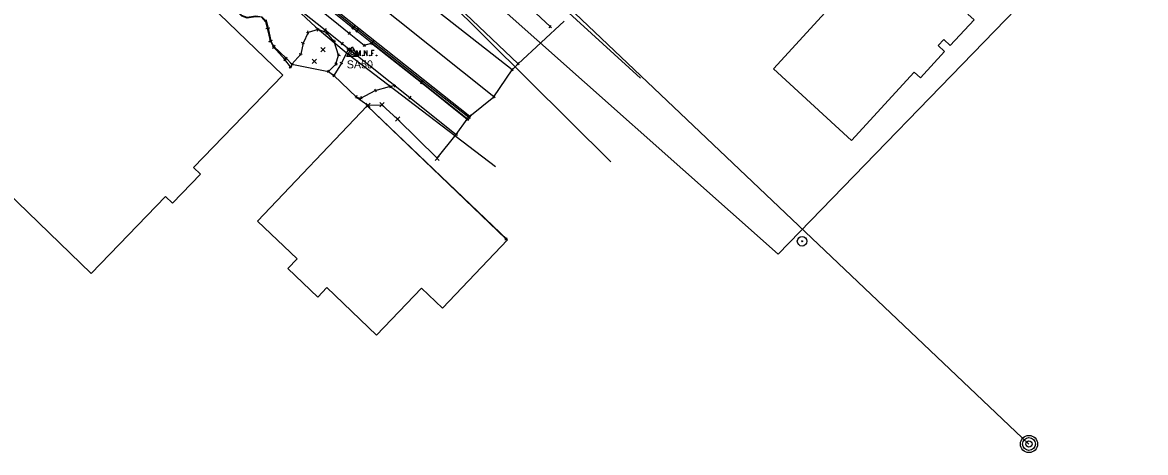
# Model space of a CAD drawing. Extents: x 1475580 to 1482245, y 377937 to 382467.
# Drawn here: x 1481461 to 1481812, y 377956 to 378090.4 of the extents above; entities that cross this region are included whole.
import ezdxf

# ---------------------------------------------------------------- set-up
doc = ezdxf.new("R2010")
doc.units = 0
for name, color, linetype in [('Default', 7, 'Continuous'), ('DT_X_Contour_Major', 7, 'Continuous'), ('DT_X_Void', 7, 'Continuous'), ('PM_P_CL_Double_Solid', 7, 'Continuous'), ('PM_X_Lane_Line', 7, 'Continuous'), ('PV_X_COP', 7, 'Continuous'), ('PV_X_Curb', 7, 'Continuous'), ('PV_X_Walk', 7, 'Continuous'), ('RD_X_Cells', 7, 'Continuous'), ('SG_X_Poles', 7, 'Continuous'), ('SG_X_PullBox', 7, 'Continuous'), ('SN_X_Private', 7, 'Continuous'), ('SN_X_Public', 7, 'Continuous'), ('SV_P_Mon_Cells_Set', 7, 'Continuous'), ('SV_X_Break_Lines', 7, 'Continuous'), ('SV_X_Shot_Marker', 7, 'Continuous'), ('SV_X_Text_Description', 7, 'Continuous'), ('SV_X_Top_of_Bank', 7, 'Continuous'), ('UT_X_Gas_Cells', 7, 'Continuous'), ('UT_X_Misc_Cells', 7, 'Continuous'), ('UT_X_Telecom_Cells', 7, 'Continuous'), ('XS_X_Ground_Line', 7, 'Continuous')]:
    doc.layers.add(name, color=color, linetype=linetype)

msp = doc.modelspace()

# ---------------------------------------------------------------- linework, layer by layer
at = {"layer": 'Default'}
for p, q in [((1481509.14, 378185.06), (1481697.21, 378017.96)), ((1481811.96, 378136.53), (1481697.21, 378017.96)), ((1481586.55, 378104.72), (1481644.93, 378046.85))]:
    msp.add_line(p, q, dxfattribs=at)
msp.add_lwpolyline([(1481559.68, 378163.61), (1481775.54, 377958.65)], dxfattribs=at)
at = {"layer": 'DT_X_Contour_Major'}
for points in [[(1481565.53, 378080), (1481565.53, 378081.6), (1481566.04, 378080), (1481566.53, 378081.6), (1481566.53, 378080)], [(1481567.3, 378080.21), (1481567.35, 378080.21), (1481567.39, 378080.19), (1481567.42, 378080.14), (1481567.42, 378080.07), (1481567.39, 378080.02), (1481567.35, 378080), (1481567.3, 378080), (1481567.27, 378080.02), (1481567.23, 378080.07), (1481567.23, 378080.14), (1481567.27, 378080.19), (1481567.3, 378080.21)], [(1481567.9, 378080), (1481567.9, 378081.6), (1481568.73, 378080), (1481568.73, 378081.6)], [(1481569.51, 378080.21), (1481569.57, 378080.21), (1481569.6, 378080.19), (1481569.63, 378080.14), (1481569.63, 378080.07), (1481569.6, 378080.02), (1481569.57, 378080), (1481569.51, 378080), (1481569.48, 378080.02), (1481569.45, 378080.07), (1481569.45, 378080.14), (1481569.48, 378080.19), (1481569.51, 378080.21)], [(1481570.88, 378081.6), (1481570.12, 378081.6), (1481570.12, 378080)], [(1481570.12, 378080.82), (1481570.66, 378080.82)], [(1481571.66, 378080.21), (1481571.72, 378080.21), (1481571.75, 378080.19), (1481571.78, 378080.14), (1481571.78, 378080.07), (1481571.75, 378080.02), (1481571.72, 378080), (1481571.66, 378080), (1481571.63, 378080.02), (1481571.6, 378080.07), (1481571.6, 378080.14), (1481571.63, 378080.19), (1481571.66, 378080.21)]]:
    msp.add_lwpolyline(points, dxfattribs=at)
msp.add_circle((1481564.09, 378080.81), 0.497, dxfattribs=at)
at = {"layer": 'DT_X_Void'}
for p, q in [((1481562.36, 378079.81), (1481564.09, 378082.81)), ((1481565.83, 378079.81), (1481562.36, 378079.81)), ((1481564.09, 378082.81), (1481565.83, 378079.81)), ((1481564.09, 378080.81), (1481564.09, 378080.81))]:
    msp.add_line(p, q, dxfattribs=at)
msp.add_circle((1481564.09, 378080.81), 1, dxfattribs=at)
at = {"layer": 'PM_P_CL_Double_Solid'}
msp.add_lwpolyline([(1481328.89, 378378.54), (1481440.38, 378283.94), (1481522.63, 378196), (1481603.5, 378119.27), (1481654.2, 378073)], dxfattribs=at)
at = {"layer": 'PM_X_Lane_Line'}
for radius in [1.5, 0.16]:
    msp.add_circle((1481704.65, 378022.02), radius, dxfattribs=at)
at = {"layer": 'PV_X_COP'}
for points in [[(1481562.85, 378081.94), (1481560.71, 378077.68), (1481558.31, 378073.83)], [(1481565.37, 378067.11), (1481566.71, 378066.77), (1481571.28, 378069.14), (1481575.74, 378070.41), (1481577.18, 378070.68)]]:
    msp.add_lwpolyline(points, dxfattribs=at)
at = {"layer": 'PV_X_Curb'}
for p, q in [((1481554.28, 378081.26), (1481555.61, 378082.6)), ((1481554.28, 378082.6), (1481555.61, 378081.26)), ((1481551.56, 378077.62), (1481552.9, 378078.95)), ((1481551.56, 378078.95), (1481552.9, 378077.62)), ((1481568.31, 378063.84), (1481569.64, 378065.18)), ((1481568.31, 378065.18), (1481569.64, 378063.84)), ((1481572.68, 378064.01), (1481574.01, 378065.35)), ((1481572.68, 378065.35), (1481574.01, 378064.01)), ((1481577.57, 378059.55), (1481578.91, 378060.89)), ((1481577.57, 378060.89), (1481578.91, 378059.55)), ((1481589.94, 378047.3), (1481591.27, 378048.64)), ((1481589.94, 378048.64), (1481591.27, 378047.3))]:
    msp.add_line(p, q, dxfattribs=at)
at = {"layer": 'PV_X_Walk'}
for p, q in [((1481775.54, 377960.65), (1481775.54, 377960.65)), ((1481775.54, 377958.65), (1481775.54, 377958.65)), ((1481775.54, 377958.65), (1481775.54, 377958.65)), ((1481775.54, 377958.65), (1481775.54, 377958.65)), ((1481775.54, 377956.65), (1481775.54, 377956.65))]:
    msp.add_line(p, q, dxfattribs=at)
msp.add_circle((1481775.54, 377958.65), 2, dxfattribs=at)
at = {"layer": 'RD_X_Cells'}
for points in [[(1481458.52, 378183.21), (1481462.55, 378180.65), (1481464.81, 378178.65), (1481466.55, 378177.09), (1481469.53, 378174.15), (1481471.49, 378172.33), (1481472.88, 378171.04), (1481473.75, 378170.22), (1481472.82, 378168.55), (1481490.35, 378151.83), (1481495.08, 378147.37), (1481513.59, 378129.71), (1481521.15, 378122.57), (1481534.36, 378110.14), (1481539.71, 378105.82), (1481558.14, 378091.1), (1481563.12, 378087.08), (1481567.81, 378083.28), (1481570.12, 378083.9), (1481585.68, 378071.65), (1481600.01, 378060.19)], [(1481460.59, 378174.73), (1481462.49, 378172.93), (1481465.52, 378170.07), (1481467.45, 378168.13), (1481469.02, 378166.75), (1481469.94, 378165.76), (1481487.85, 378148.78), (1481492.26, 378144.63), (1481510.84, 378126.93), (1481518.37, 378119.73), (1481531.89, 378107.04), (1481537.21, 378102.75), (1481555.6, 378088.12), (1481560.89, 378083.85), (1481563.14, 378082.04), (1481582.04, 378066.96), (1481596.55, 378055.44)]]:
    msp.add_lwpolyline(points, dxfattribs=at)
at = {"layer": 'SG_X_Poles'}
msp.add_lwpolyline([(1481443.23, 378191.33), (1481460.58, 378174.71), (1481460.58, 378174.71), (1481552.62, 378089.05), (1481562.79, 378080.54), (1481608.89, 378045.37)], dxfattribs=at)
at = {"layer": 'SG_X_PullBox'}
for radius in [2.67, 2, 1]:
    msp.add_circle((1481775.54, 377958.65), radius, dxfattribs=at)
at = {"layer": 'SN_X_Private'}
msp.add_lwpolyline([(1481556.67, 378075.13), (1481558.99, 378077.38), (1481559.83, 378080.22), (1481558.44, 378084.49), (1481556.16, 378087.15), (1481553.46, 378088.2), (1481550.29, 378087.28), (1481548.7, 378083.9), (1481547.99, 378080.54), (1481545.19, 378077.34), (1481543.4, 378079.23), (1481539.6, 378082.91), (1481538.67, 378084.61), (1481537.82, 378088.62), (1481537.33, 378090.71), (1481535.9, 378092.09), (1481533.85, 378092.42), (1481531.25, 378091.92), (1481529.54, 378092.55), (1481525.83, 378096.48)], dxfattribs=at)
at = {"layer": 'SN_X_Public'}
msp.add_lwpolyline([(1481608.37, 378067.18), (1481558.31, 378107.18), (1481537.72, 378124.16), (1481479.82, 378179.17)], dxfattribs=at)
at = {"layer": 'SV_P_Mon_Cells_Set'}
for points in [[(1481451.97, 378161.26), (1481473.67, 378140.29), (1481475.51, 378142.19), (1481484.73, 378133.29), (1481482.89, 378131.39), (1481542.37, 378073.94), (1481514.51, 378045.1), (1481516.7, 378042.98), (1481507.91, 378033.89), (1481505.73, 378035.99), (1481482.51, 378011.95), (1481423.22, 378069.23), (1481422, 378067.97), (1481413.02, 378076.65), (1481414.23, 378077.9), (1481392.1, 378099.28)], [(1481752.53, 378137.81), (1481775.2, 378116.97), (1481774.2, 378115.07), (1481772.46, 378110.43), (1481756.45, 378093.02), (1481758.37, 378091.26), (1481750.96, 378083.2), (1481748.91, 378085.09), (1481747.15, 378083.18), (1481749.17, 378081.33), (1481741.6, 378073.1), (1481739.7, 378074.84), (1481720.13, 378053.55), (1481695.75, 378075.96), (1481713.04, 378094.77), (1481710.72, 378096.9), (1481717.63, 378104.41), (1481719.97, 378102.26), (1481727.98, 378110.97), (1481725.96, 378112.83), (1481733, 378120.48), (1481734.95, 378118.69)], [(1481612.64, 378022.48), (1481592.25, 378001.1), (1481585.69, 378007.35), (1481571.67, 377992.66), (1481556.09, 378007.52), (1481553.28, 378004.58), (1481543.94, 378013.49), (1481546.82, 378016.52), (1481534.44, 378028.33), (1481568.76, 378064.32)]]:
    msp.add_lwpolyline(points, close=True, dxfattribs=at)
msp.add_lwpolyline([(1481568.76, 378064.32), (1481612.1, 378022.77)], dxfattribs=at)
at = {"layer": 'SV_X_Break_Lines'}
for points in [[(1481614.01, 378075.61), (1481567.93, 378111.83), (1481558.93, 378119.06), (1481551.14, 378125.65), (1481539.73, 378135.95), (1481513.59, 378160.95), (1481485.53, 378187.47)], [(1481615.92, 378077.49), (1481566.67, 378124.35), (1481560.41, 378129.93), (1481553.77, 378135), (1481547.01, 378139.33), (1481513.59, 378160.95)]]:
    msp.add_lwpolyline(points, dxfattribs=at)
at = {"layer": 'SV_X_Shot_Marker'}
msp.add_lwpolyline([(1481473.05, 378172.31), (1481522.89, 378125.39), (1481530.28, 378118.34), (1481538.45, 378111.25), (1481547.66, 378103.47), (1481557.62, 378095.38), (1481600.78, 378061.17)], dxfattribs=at)
at = {"layer": 'SV_X_Text_Description'}
msp.add_lwpolyline([(1481522.36, 378124.13), (1481535.77, 378111.48), (1481540.63, 378107.49), (1481559.35, 378092.66), (1481564.22, 378088.75), (1481565.47, 378087.79), (1481570.18, 378084.03), (1481585.76, 378071.75), (1481600.14, 378060.3)], dxfattribs=at)
at = {"layer": 'SV_X_Top_of_Bank'}
msp.add_lwpolyline([(1481537.33, 378090.71), (1481537.82, 378088.62), (1481538.67, 378084.61), (1481539.6, 378082.91), (1481543.4, 378079.23), (1481545.19, 378077.34), (1481556.67, 378075.13), (1481558.31, 378073.83), (1481565.37, 378067.11), (1481568.98, 378064.51), (1481573.34, 378064.68), (1481578.24, 378060.22), (1481590.61, 378047.97), (1481596.55, 378055.44), (1481600.01, 378060.19), (1481600.14, 378060.3), (1481600.51, 378060.76), (1481600.78, 378061.17), (1481608.37, 378067.18), (1481614.01, 378075.61), (1481615.92, 378077.49), (1481630.31, 378090.85)], dxfattribs=at)
at = {"layer": 'UT_X_Gas_Cells'}
for p, q in [((1481537.24, 378090.15), (1481537.01, 378091.12)), ((1481537.45, 378090.23), (1481537.22, 378091.2)), ((1481537.12, 378088.5), (1481538.1, 378088.72)), ((1481537.33, 378088.51), (1481538.31, 378088.72)), ((1481537.72, 378088.12), (1481537.5, 378089.09)), ((1481537.61, 378088.61), (1481537.61, 378088.61)), ((1481537.93, 378088.13), (1481537.72, 378089.11)), ((1481537.82, 378088.62), (1481537.82, 378088.62)), ((1481550.77, 378087.42), (1481549.81, 378087.13)), ((1481550.43, 378086.8), (1481550.15, 378087.75)), ((1481550.29, 378087.28), (1481550.29, 378087.28)), ((1481553.92, 378088.02), (1481552.99, 378088.38)), ((1481553.27, 378087.73), (1481553.64, 378088.66)), ((1481553.46, 378088.2), (1481553.46, 378088.2)), ((1481555.21, 378088.43), (1481555.99, 378087.8)), ((1481555.91, 378088.51), (1481555.28, 378087.72)), ((1481555.6, 378088.12), (1481555.6, 378088.12)), ((1481555.78, 378086.82), (1481556.54, 378087.47)), ((1481556.48, 378086.77), (1481555.83, 378087.53)), ((1481556.16, 378087.15), (1481556.16, 378087.15)), ((1481562.73, 378087.39), (1481563.51, 378086.77)), ((1481563.43, 378087.47), (1481562.8, 378086.69)), ((1481563.12, 378087.08), (1481563.12, 378087.08)), ((1481563.83, 378089.06), (1481564.61, 378088.43)), ((1481564.54, 378089.14), (1481563.91, 378088.36)), ((1481564.22, 378088.75), (1481564.22, 378088.75)), ((1481564.28, 378089.38), (1481565.06, 378088.76)), ((1481564.98, 378089.46), (1481564.36, 378088.68)), ((1481564.67, 378089.07), (1481564.67, 378089.07)), ((1481565.08, 378088.09), (1481565.87, 378087.48)), ((1481565.78, 378088.18), (1481565.17, 378087.39)), ((1481565.46, 378088.47), (1481566.26, 378087.86)), ((1481565.47, 378087.79), (1481565.47, 378087.79)), ((1481566.16, 378088.56), (1481565.56, 378087.77)), ((1481565.86, 378088.17), (1481565.86, 378088.17)), ((1481626.29, 378088.76), (1481625.56, 378089.44)), ((1481625.59, 378088.73), (1481626.27, 378089.47)), ((1481625.93, 378089.1), (1481625.93, 378089.1)), ((1481538.06, 378084.44), (1481538.95, 378084.9)), ((1481538.23, 378084.38), (1481539.11, 378084.85)), ((1481538.74, 378084.23), (1481538.28, 378085.12)), ((1481538.91, 378084.18), (1481538.43, 378085.05)), ((1481538.51, 378084.67), (1481538.51, 378084.67)), ((1481538.67, 378084.61), (1481538.67, 378084.61)), ((1481539.96, 378082.56), (1481539.24, 378083.26)), ((1481539.25, 378082.55), (1481539.95, 378083.27)), ((1481549.15, 378083.69), (1481548.25, 378084.12)), ((1481548.91, 378084.36), (1481548.48, 378083.45)), ((1481548.7, 378083.9), (1481548.7, 378083.9)), ((1481557.97, 378084.33), (1481558.92, 378084.64)), ((1481558.6, 378084.01), (1481558.29, 378084.96)), ((1481558.44, 378084.49), (1481558.44, 378084.49)), ((1481560.5, 378084.16), (1481561.28, 378083.53)), ((1481561.21, 378084.24), (1481560.58, 378083.46)), ((1481560.89, 378083.85), (1481560.89, 378083.85)), ((1481567.42, 378083.6), (1481568.2, 378082.97)), ((1481568.13, 378083.67), (1481567.5, 378082.89)), ((1481567.81, 378083.28), (1481567.81, 378083.28)), ((1481569.64, 378083.77), (1481570.6, 378084.03)), ((1481569.79, 378084.34), (1481570.57, 378083.72)), ((1481570.49, 378084.42), (1481569.87, 378083.64)), ((1481569.99, 378084.38), (1481570.25, 378083.42)), ((1481570.12, 378083.9), (1481570.12, 378083.9)), ((1481570.16, 378084.81), (1481570.95, 378084.19)), ((1481570.18, 378084.03), (1481570.18, 378084.03)), ((1481570.86, 378084.89), (1481570.25, 378084.1)), ((1481570.56, 378084.5), (1481570.56, 378084.5)), ((1481539.19, 378082.3), (1481539.93, 378082.98)), ((1481539.9, 378082.27), (1481539.22, 378083.01)), ((1481539.56, 378082.64), (1481539.56, 378082.64)), ((1481539.6, 378082.91), (1481539.6, 378082.91)), ((1481543.03, 378078.89), (1481543.76, 378079.58)), ((1481543.74, 378078.87), (1481543.05, 378079.59)), ((1481548.48, 378080.44), (1481547.5, 378080.64)), ((1481548.09, 378081.03), (1481547.89, 378080.05)), ((1481547.99, 378080.54), (1481547.99, 378080.54)), ((1481559.35, 378080.36), (1481560.31, 378080.08)), ((1481559.69, 378079.74), (1481559.97, 378080.7)), ((1481559.83, 378080.22), (1481559.83, 378080.22)), ((1481563.29, 378081.72), (1481562.4, 378082.17)), ((1481563.07, 378082.39), (1481562.62, 378081.5)), ((1481562.75, 378082.35), (1481563.53, 378081.73)), ((1481563.45, 378082.43), (1481562.82, 378081.65)), ((1481562.85, 378081.94), (1481562.85, 378081.94)), ((1481563.14, 378082.04), (1481563.14, 378082.04)), ((1481542.65, 378078.52), (1481543.45, 378079.13)), ((1481543.35, 378078.43), (1481542.75, 378079.23)), ((1481543.05, 378078.83), (1481543.05, 378078.83)), ((1481543.4, 378079.23), (1481543.4, 378079.23)), ((1481544.36, 378076.26), (1481545.16, 378076.87)), ((1481545.06, 378076.17), (1481544.46, 378076.96)), ((1481544.76, 378076.56), (1481544.76, 378076.56)), ((1481545.57, 378077.01), (1481544.81, 378077.67)), ((1481545.52, 378077.71), (1481544.86, 378076.96)), ((1481545.19, 378077.34), (1481545.19, 378077.34)), ((1481558.63, 378077.03), (1481559.35, 378077.73)), ((1481558.64, 378077.74), (1481559.33, 378077.02)), ((1481558.99, 378077.38), (1481558.99, 378077.38)), ((1481561.16, 378077.45), (1481560.27, 378077.9)), ((1481560.94, 378078.13), (1481560.49, 378077.23)), ((1481560.71, 378077.68), (1481560.71, 378077.68)), ((1481616.28, 378077.15), (1481615.56, 378077.84)), ((1481615.58, 378077.13), (1481616.27, 378077.86)), ((1481615.92, 378077.49), (1481615.92, 378077.49)), ((1481556.31, 378074.79), (1481557.03, 378075.48)), ((1481556.32, 378075.49), (1481557.01, 378074.77)), ((1481556.67, 378075.13), (1481556.67, 378075.13)), ((1481558.73, 378073.57), (1481557.88, 378074.1)), ((1481558.57, 378074.26), (1481558.04, 378073.41)), ((1481558.31, 378073.83), (1481558.31, 378073.83)), ((1481585.63, 378072.52), (1481586.41, 378071.9)), ((1481586.33, 378072.6), (1481585.71, 378071.82)), ((1481614.41, 378075.3), (1481613.62, 378075.92)), ((1481613.7, 378075.22), (1481614.32, 378076)), ((1481614.01, 378075.61), (1481614.01, 378075.61)), ((1481570.84, 378068.91), (1481571.73, 378069.37)), ((1481571.05, 378069.58), (1481571.51, 378068.69)), ((1481571.28, 378069.14), (1481571.28, 378069.14)), ((1481575.26, 378070.27), (1481576.22, 378070.55)), ((1481575.6, 378070.89), (1481575.88, 378069.93)), ((1481575.74, 378070.41), (1481575.74, 378070.41)), ((1481576.69, 378070.59), (1481577.67, 378070.77)), ((1481577.09, 378071.17), (1481577.27, 378070.19)), ((1481577.18, 378070.68), (1481577.18, 378070.68)), ((1481585.28, 378071.96), (1481586.07, 378071.34)), ((1481585.37, 378072.06), (1481586.15, 378071.44)), ((1481585.99, 378072.04), (1481585.37, 378071.25)), ((1481586.07, 378072.14), (1481585.45, 378071.36)), ((1481585.68, 378071.65), (1481585.68, 378071.65)), ((1481585.76, 378071.75), (1481585.76, 378071.75)), ((1481586.02, 378072.21), (1481586.02, 378072.21)), ((1481564.89, 378067.23), (1481565.86, 378066.98)), ((1481565.5, 378067.59), (1481565.25, 378066.62)), ((1481565.37, 378067.11), (1481565.37, 378067.11)), ((1481566.23, 378066.89), (1481567.2, 378066.65)), ((1481566.84, 378067.25), (1481566.59, 378066.28)), ((1481566.71, 378066.77), (1481566.71, 378066.77)), ((1481581.65, 378067.28), (1481582.43, 378066.65)), ((1481582.35, 378067.36), (1481581.73, 378066.57)), ((1481582.04, 378066.96), (1481582.04, 378066.96)), ((1481608.76, 378066.87), (1481607.98, 378067.49)), ((1481608.06, 378066.79), (1481608.68, 378067.57)), ((1481608.37, 378067.18), (1481608.37, 378067.18)), ((1481568.4, 378064.67), (1481569.13, 378063.97)), ((1481569.11, 378064.68), (1481568.42, 378063.96)), ((1481568.76, 378064.32), (1481568.76, 378064.32)), ((1481599.62, 378060.5), (1481600.4, 378059.88)), ((1481600.32, 378060.58), (1481599.7, 378059.8)), ((1481599.75, 378060.61), (1481600.53, 378059.99)), ((1481600.45, 378060.69), (1481599.83, 378059.91)), ((1481600.01, 378060.19), (1481600.01, 378060.19)), ((1481600.12, 378061.07), (1481600.9, 378060.44)), ((1481600.14, 378060.3), (1481600.14, 378060.3)), ((1481600.82, 378061.15), (1481600.2, 378060.36)), ((1481600.38, 378061.48), (1481601.17, 378060.86)), ((1481601.09, 378061.56), (1481600.46, 378060.78)), ((1481600.51, 378060.76), (1481600.51, 378060.76)), ((1481600.78, 378061.17), (1481600.78, 378061.17)), ((1481596.16, 378055.75), (1481596.94, 378055.13)), ((1481596.86, 378055.83), (1481596.24, 378055.05)), ((1481596.55, 378055.44), (1481596.55, 378055.44)), ((1481611.74, 378023.11), (1481612.46, 378022.42)), ((1481612.45, 378023.13), (1481611.76, 378022.4)), ((1481612.1, 378022.77), (1481612.1, 378022.77))]:
    msp.add_line(p, q, dxfattribs=at)
at = {"layer": 'UT_X_Misc_Cells'}
msp.add_lwpolyline([(1481544.76, 378076.56), (1481543.05, 378078.83), (1481539.56, 378082.64), (1481538.51, 378084.67), (1481537.61, 378088.61), (1481537.12, 378090.63), (1481535.84, 378092.02), (1481533.84, 378092.16), (1481531.28, 378091.74), (1481529.57, 378092.34), (1481525.67, 378096.09)], dxfattribs=at)
at = {"layer": 'UT_X_Telecom_Cells'}
msp.add_lwpolyline([(1481625.93, 378089.1), (1481583.02, 378129.12)], dxfattribs=at)
at = {"layer": 'XS_X_Ground_Line'}
msp.add_lwpolyline([(1481458.94, 378183.75), (1481462.96, 378181.17), (1481465.23, 378179.21), (1481466.97, 378177.55), (1481469.91, 378174.8), (1481471.97, 378172.78), (1481473.34, 378171.52), (1481474.19, 378170.66), (1481492.07, 378153.75), (1481496.71, 378149.33), (1481515.25, 378131.7), (1481518.52, 378128.67), (1481519.59, 378129.72), (1481523.38, 378126.07), (1481522.36, 378124.96), (1481536.09, 378111.96), (1481540.93, 378107.87), (1481559.68, 378093.06), (1481564.67, 378089.07), (1481565.86, 378088.17), (1481570.56, 378084.5), (1481586.02, 378072.21), (1481600.51, 378060.76)], dxfattribs=at)

# ---------------------------------------------------------------- texts
at = {"layer": 'Default'}
msp.add_text('SA50', height=2.5, dxfattribs=at).set_placement((1481562.37, 378076.06))

doc.saveas('drawing.dxf')
